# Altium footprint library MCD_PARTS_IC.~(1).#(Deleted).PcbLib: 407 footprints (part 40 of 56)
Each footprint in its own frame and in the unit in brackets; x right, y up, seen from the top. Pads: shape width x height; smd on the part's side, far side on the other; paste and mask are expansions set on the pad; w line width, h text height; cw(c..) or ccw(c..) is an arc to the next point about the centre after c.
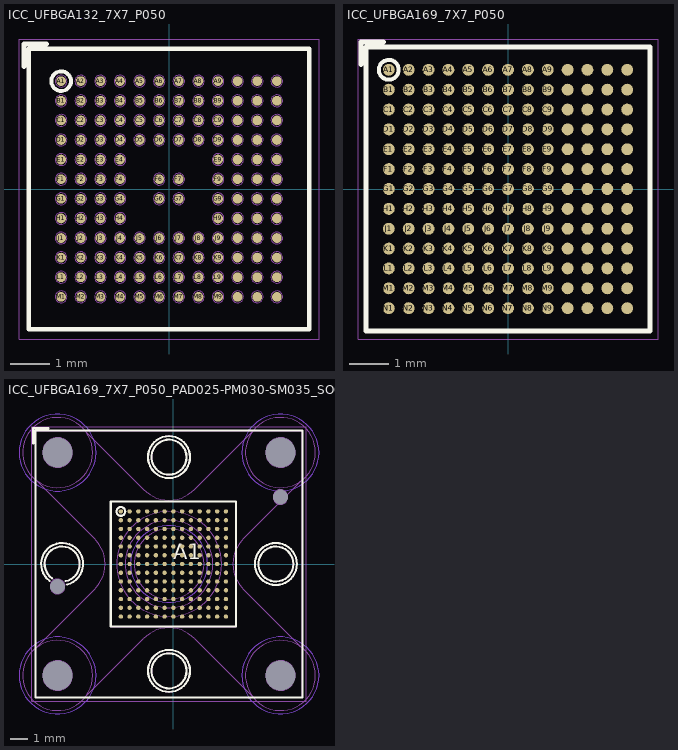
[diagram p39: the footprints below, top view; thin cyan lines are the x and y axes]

## ICC_UFBGA132_7X7_P050 [mm] "IPC"
height 0.6
pads (132):
  round 0.25 smd mask+0.05: A1(-2.75,2.75) A2(-2.25,2.75) A3(-1.75,2.75) A4(-1.25,2.75) A5(-0.75,2.75) A6(-0.25,2.75) A7(0.25,2.75) A8(0.75,2.75) A9(1.25,2.75) A10(1.75,2.75) A11(2.25,2.75) A12(2.75,2.75) B1(-2.75,2.25) B2(-2.25,2.25) B3(-1.75,2.25) B4(-1.25,2.25) B5(-0.75,2.25) B6(-0.25,2.25) B7(0.25,2.25) B8(0.75,2.25) B9(1.25,2.25) B10(1.75,2.25) B11(2.25,2.25) B12(2.75,2.25) C1(-2.75,1.75) C2(-2.25,1.75) C3(-1.75,1.75) C4(-1.25,1.75) C5(-0.75,1.75) C6(-0.25,1.75) C7(0.25,1.75) C8(0.75,1.75) C9(1.25,1.75) C10(1.75,1.75) C11(2.25,1.75) C12(2.75,1.75) D1(-2.75,1.25) D2(-2.25,1.25) D3(-1.75,1.25) D4(-1.25,1.25) D5(-0.75,1.25) D6(-0.25,1.25) D7(0.25,1.25) D8(0.75,1.25) D9(1.25,1.25) D10(1.75,1.25) D11(2.25,1.25) D12(2.75,1.25) E1(-2.75,0.75) E2(-2.25,0.75) E3(-1.75,0.75) E4(-1.25,0.75) E9(1.25,0.75) E10(1.75,0.75) E11(2.25,0.75) E12(2.75,0.75) F1(-2.75,0.25) F2(-2.25,0.25) F3(-1.75,0.25) F4(-1.25,0.25) F6(-0.25,0.25) F7(0.25,0.25) F9(1.25,0.25) F10(1.75,0.25) F11(2.25,0.25) F12(2.75,0.25) G1(-2.75,-0.25) G2(-2.25,-0.25) G3(-1.75,-0.25) G4(-1.25,-0.25) G6(-0.25,-0.25) G7(0.25,-0.25) G9(1.25,-0.25) G10(1.75,-0.25) G11(2.25,-0.25) G12(2.75,-0.25) H1(-2.75,-0.75) H2(-2.25,-0.75) H3(-1.75,-0.75) H4(-1.25,-0.75) H9(1.25,-0.75) H10(1.75,-0.75) H11(2.25,-0.75) H12(2.75,-0.75) J1(-2.75,-1.25) J2(-2.25,-1.25) J3(-1.75,-1.25) J4(-1.25,-1.25) J5(-0.75,-1.25) J6(-0.25,-1.25) J7(0.25,-1.25) J8(0.75,-1.25) J9(1.25,-1.25) J10(1.75,-1.25) J11(2.25,-1.25) J12(2.75,-1.25) K1(-2.75,-1.75) K2(-2.25,-1.75) K3(-1.75,-1.75) K4(-1.25,-1.75) K5(-0.75,-1.75) K6(-0.25,-1.75) K7(0.25,-1.75) K8(0.75,-1.75) K9(1.25,-1.75) K10(1.75,-1.75) K11(2.25,-1.75) K12(2.75,-1.75) L1(-2.75,-2.25) L2(-2.25,-2.25) L3(-1.75,-2.25) L4(-1.25,-2.25) L5(-0.75,-2.25) L6(-0.25,-2.25) L7(0.25,-2.25) L8(0.75,-2.25) L9(1.25,-2.25) L10(1.75,-2.25) L11(2.25,-2.25) L12(2.75,-2.25) M1(-2.75,-2.75) M2(-2.25,-2.75) M3(-1.75,-2.75) M4(-1.25,-2.75) M5(-0.75,-2.75) M6(-0.25,-2.75) M7(0.25,-2.75) M8(0.75,-2.75) M9(1.25,-2.75) M10(1.75,-2.75) M11(2.25,-2.75) M12(2.75,-2.75)
Top Overlay:
  circle w0.1: c-2.75,2.75 r0.25
  lines w0.12: -3.7,3.125 -3.7,3.7 -3.125,3.7 ; -3.575,-3.575 3.575,-3.575 3.575,3.575 -3.575,3.575 -3.575,-3.575
M14-Top Assembly:
  circle w0.01: c-2.75,2.75 r0.15
  circle w0.01: c-2.25,2.75 r0.15
  circle w0.01: c-1.75,2.75 r0.15
  circle w0.01: c-1.25,2.75 r0.15
  circle w0.01: c-0.75,2.75 r0.15
  circle w0.01: c-0.25,2.75 r0.15
  circle w0.01: c0.25,2.75 r0.15
  circle w0.01: c0.75,2.75 r0.15
  circle w0.01: c1.25,2.75 r0.15
  circle w0.01: c1.75,2.75 r0.15
  circle w0.01: c2.25,2.75 r0.15
  circle w0.01: c2.75,2.75 r0.15
  circle w0.01: c2.75,2.25 r0.15
  circle w0.01: c2.25,2.25 r0.15
  circle w0.01: c1.75,2.25 r0.15
  circle w0.01: c1.25,2.25 r0.15
  circle w0.01: c0.75,2.25 r0.15
  circle w0.01: c0.25,2.25 r0.15
  circle w0.01: c-0.25,2.25 r0.15
  circle w0.01: c-0.75,2.25 r0.15
  circle w0.01: c-1.25,2.25 r0.15
  circle w0.01: c-1.75,2.25 r0.15
  circle w0.01: c-2.25,2.25 r0.15
  circle w0.01: c-2.75,2.25 r0.15
  circle w0.01: c2.75,1.75 r0.15
  circle w0.01: c2.25,1.75 r0.15
  circle w0.01: c1.75,1.75 r0.15
  circle w0.01: c1.25,1.75 r0.15
  circle w0.01: c0.75,1.75 r0.15
  circle w0.01: c0.25,1.75 r0.15
  circle w0.01: c-0.25,1.75 r0.15
  circle w0.01: c-0.75,1.75 r0.15
  circle w0.01: c-1.25,1.75 r0.15
  circle w0.01: c-1.75,1.75 r0.15
  circle w0.01: c-2.25,1.75 r0.15
  circle w0.01: c-2.75,1.75 r0.15
  circle w0.01: c2.75,1.25 r0.15
  circle w0.01: c2.25,1.25 r0.15
  circle w0.01: c1.75,1.25 r0.15
  circle w0.01: c1.25,1.25 r0.15
  circle w0.01: c0.75,1.25 r0.15
  circle w0.01: c0.25,1.25 r0.15
  circle w0.01: c-0.25,1.25 r0.15
  circle w0.01: c-0.75,1.25 r0.15
  circle w0.01: c-1.25,1.25 r0.15
  circle w0.01: c-1.75,1.25 r0.15
  circle w0.01: c-2.25,1.25 r0.15
  circle w0.01: c-2.75,1.25 r0.15
  circle w0.01: c-2.75,-2.75 r0.15
  circle w0.01: c-2.25,-2.75 r0.15
  circle w0.01: c-1.75,-2.75 r0.15
  circle w0.01: c-1.25,-2.75 r0.15
  circle w0.01: c-0.75,-2.75 r0.15
  circle w0.01: c-0.25,-2.75 r0.15
  circle w0.01: c0.25,-2.75 r0.15
  circle w0.01: c0.75,-2.75 r0.15
  circle w0.01: c1.25,-2.75 r0.15
  circle w0.01: c1.75,-2.75 r0.15
  circle w0.01: c2.25,-2.75 r0.15
  circle w0.01: c2.75,-2.75 r0.15
  circle w0.01: c-2.75,-2.25 r0.15
  circle w0.01: c-2.25,-2.25 r0.15
  circle w0.01: c-1.75,-2.25 r0.15
  circle w0.01: c-1.25,-2.25 r0.15
  circle w0.01: c-0.75,-2.25 r0.15
  circle w0.01: c-0.25,-2.25 r0.15
  circle w0.01: c0.25,-2.25 r0.15
  circle w0.01: c0.75,-2.25 r0.15
  circle w0.01: c1.25,-2.25 r0.15
  circle w0.01: c1.75,-2.25 r0.15
  circle w0.01: c2.25,-2.25 r0.15
  circle w0.01: c2.75,-2.25 r0.15
  circle w0.01: c-2.75,-1.75 r0.15
  circle w0.01: c-2.25,-1.75 r0.15
  circle w0.01: c-1.75,-1.75 r0.15
  circle w0.01: c-1.25,-1.75 r0.15
  circle w0.01: c-0.75,-1.75 r0.15
  circle w0.01: c-0.25,-1.75 r0.15
  circle w0.01: c0.25,-1.75 r0.15
  circle w0.01: c0.75,-1.75 r0.15
  circle w0.01: c1.25,-1.75 r0.15
  circle w0.01: c1.75,-1.75 r0.15
  circle w0.01: c2.25,-1.75 r0.15
  circle w0.01: c2.75,-1.75 r0.15
  circle w0.01: c2.75,-1.25 r0.15
  circle w0.01: c2.25,-1.25 r0.15
  circle w0.01: c1.75,-1.25 r0.15
  circle w0.01: c1.25,-1.25 r0.15
  circle w0.01: c0.75,-1.25 r0.15
  circle w0.01: c0.25,-1.25 r0.15
  circle w0.01: c-0.25,-1.25 r0.15
  circle w0.01: c-0.75,-1.25 r0.15
  circle w0.01: c-1.25,-1.25 r0.15
  circle w0.01: c-1.75,-1.25 r0.15
  circle w0.01: c-2.25,-1.25 r0.15
  circle w0.01: c-2.75,-1.25 r0.15
  circle w0.01: c-2.75,0.75 r0.15
  circle w0.01: c-2.25,0.75 r0.15
  circle w0.01: c-1.75,0.75 r0.15
  circle w0.01: c-1.25,0.75 r0.15
  circle w0.01: c-1.25,0.25 r0.15
  circle w0.01: c-1.75,0.25 r0.15
  circle w0.01: c-2.25,0.25 r0.15
  circle w0.01: c-2.75,0.25 r0.15
  circle w0.01: c-1.25,-0.25 r0.15
  circle w0.01: c-1.75,-0.25 r0.15
  circle w0.01: c-2.25,-0.25 r0.15
  circle w0.01: c-2.75,-0.25 r0.15
  circle w0.01: c-1.25,-0.75 r0.15
  circle w0.01: c-1.75,-0.75 r0.15
  circle w0.01: c-2.25,-0.75 r0.15
  circle w0.01: c-2.75,-0.75 r0.15
  circle w0.01: c1.25,0.75 r0.15
  circle w0.01: c1.75,0.75 r0.15
  circle w0.01: c2.25,0.75 r0.15
  circle w0.01: c2.75,0.75 r0.15
  circle w0.01: c2.75,0.25 r0.15
  circle w0.01: c2.25,0.25 r0.15
  circle w0.01: c1.75,0.25 r0.15
  circle w0.01: c1.25,0.25 r0.15
  circle w0.01: c2.75,-0.25 r0.15
  circle w0.01: c2.25,-0.25 r0.15
  circle w0.01: c1.75,-0.25 r0.15
  circle w0.01: c1.25,-0.25 r0.15
  circle w0.01: c2.75,-0.75 r0.15
  circle w0.01: c2.25,-0.75 r0.15
  circle w0.01: c1.75,-0.75 r0.15
  circle w0.01: c1.25,-0.75 r0.15
  circle w0.01: c0.25,0.25 r0.15
  circle w0.01: c-0.25,0.25 r0.15
  circle w0.01: c0.25,-0.25 r0.15
  circle w0.01: c-0.25,-0.25 r0.15
  lines w0.01: -3.575,-3.575 3.575,-3.575 3.575,3.575 -3.575,3.575 -3.575,-3.575
  text "A1" at -3,2.525 h0.5
  text "'.Designator'" at -2,-0.5 h0.75
M16-Top Courtyard:
  lines w0.01: -3.825,-3.825 -3.825,3.825 3.825,3.825 3.825,-3.825 -3.825,-3.825
3D body: height 0.61, standoff 0.6, extent -3.048,2.451 -2.45,3.049
3D body: height 0.6, standoff 0.15, extent -3.575,-3.575 3.575,3.575
3D body: height 0.25, standoff -0.05, extent -2.886,2.607 -2.605,2.893
3D body: height 0.25, standoff -0.05, extent -2.386,2.607 -2.105,2.893
3D body: height 0.25, standoff -0.05, extent -1.886,2.607 -1.605,2.893
3D body: height 0.25, standoff -0.05, extent -1.386,2.607 -1.105,2.893
3D body: height 0.25, standoff -0.05, extent -0.886,2.607 -0.605,2.893
3D body: height 0.25, standoff -0.05, extent -0.386,2.607 -0.105,2.893
3D body: height 0.25, standoff -0.05, extent 0.114,2.607 0.395,2.893
3D body: height 0.25, standoff -0.05, extent 0.614,2.607 0.895,2.893
3D body: height 0.25, standoff -0.05, extent 1.114,2.607 1.395,2.893
3D body: height 0.25, standoff -0.05, extent 1.614,2.607 1.895,2.893
3D body: height 0.25, standoff -0.05, extent 2.114,2.607 2.395,2.893
3D body: height 0.25, standoff -0.05, extent 2.614,2.607 2.895,2.893
3D body: height 0.25, standoff -0.05, extent -2.886,2.107 -2.605,2.393
3D body: height 0.25, standoff -0.05, extent -2.386,2.107 -2.105,2.393
3D body: height 0.25, standoff -0.05, extent -1.886,2.107 -1.605,2.393
3D body: height 0.25, standoff -0.05, extent -1.386,2.107 -1.105,2.393
3D body: height 0.25, standoff -0.05, extent -0.886,2.107 -0.605,2.393
3D body: height 0.25, standoff -0.05, extent -0.386,2.107 -0.105,2.393
3D body: height 0.25, standoff -0.05, extent 0.114,2.107 0.395,2.393
3D body: height 0.25, standoff -0.05, extent 0.614,2.107 0.895,2.393
3D body: height 0.25, standoff -0.05, extent 1.114,2.107 1.395,2.393
3D body: height 0.25, standoff -0.05, extent 1.614,2.107 1.895,2.393
3D body: height 0.25, standoff -0.05, extent 2.114,2.107 2.395,2.393
3D body: height 0.25, standoff -0.05, extent 2.614,2.107 2.895,2.393
3D body: height 0.25, standoff -0.05, extent -0.886,1.607 -0.605,1.893
3D body: height 0.25, standoff -0.05, extent -1.386,1.607 -1.105,1.893
3D body: height 0.25, standoff -0.05, extent -1.886,1.607 -1.605,1.893
3D body: height 0.25, standoff -0.05, extent -2.386,1.607 -2.105,1.893
3D body: height 0.25, standoff -0.05, extent -2.886,1.607 -2.605,1.893
3D body: height 0.25, standoff -0.05, extent -0.386,1.607 -0.105,1.893
3D body: height 0.25, standoff -0.05, extent 0.114,1.607 0.395,1.893
3D body: height 0.25, standoff -0.05, extent 0.614,1.607 0.895,1.893
3D body: height 0.25, standoff -0.05, extent 1.114,1.607 1.395,1.893
3D body: height 0.25, standoff -0.05, extent 1.614,1.607 1.895,1.893
3D body: height 0.25, standoff -0.05, extent 2.114,1.607 2.395,1.893
3D body: height 0.25, standoff -0.05, extent 2.614,1.607 2.895,1.893
3D body: height 0.25, standoff -0.05, extent -0.886,1.107 -0.605,1.393
3D body: height 0.25, standoff -0.05, extent -1.386,1.107 -1.105,1.393
3D body: height 0.25, standoff -0.05, extent -1.886,1.107 -1.605,1.393
3D body: height 0.25, standoff -0.05, extent -2.386,1.107 -2.105,1.393
3D body: height 0.25, standoff -0.05, extent -2.886,1.107 -2.605,1.393
3D body: height 0.25, standoff -0.05, extent -0.386,1.107 -0.105,1.393
3D body: height 0.25, standoff -0.05, extent 0.114,1.107 0.395,1.393
3D body: height 0.25, standoff -0.05, extent 0.614,1.107 0.895,1.393
3D body: height 0.25, standoff -0.05, extent 1.114,1.107 1.395,1.393
3D body: height 0.25, standoff -0.05, extent 1.614,1.107 1.895,1.393
3D body: height 0.25, standoff -0.05, extent 2.114,1.107 2.395,1.393
3D body: height 0.25, standoff -0.05, extent 2.614,1.107 2.895,1.393
3D body: height 0.25, standoff -0.05, extent -0.886,-1.393 -0.605,-1.107
3D body: height 0.25, standoff -0.05, extent -1.386,-1.393 -1.105,-1.107
3D body: height 0.25, standoff -0.05, extent -1.886,-1.393 -1.605,-1.107
3D body: height 0.25, standoff -0.05, extent -2.386,-1.393 -2.105,-1.107
3D body: height 0.25, standoff -0.05, extent -2.886,-1.393 -2.605,-1.107
3D body: height 0.25, standoff -0.05, extent -0.386,-1.393 -0.105,-1.107
3D body: height 0.25, standoff -0.05, extent 0.114,-1.393 0.395,-1.107
3D body: height 0.25, standoff -0.05, extent 0.614,-1.393 0.895,-1.107
3D body: height 0.25, standoff -0.05, extent 1.114,-1.393 1.395,-1.107
3D body: height 0.25, standoff -0.05, extent 1.614,-1.393 1.895,-1.107
3D body: height 0.25, standoff -0.05, extent 2.114,-1.393 2.395,-1.107
3D body: height 0.25, standoff -0.05, extent 2.614,-1.393 2.895,-1.107
3D body: height 0.25, standoff -0.05, extent -0.886,-1.893 -0.605,-1.607
3D body: height 0.25, standoff -0.05, extent -1.386,-1.893 -1.105,-1.607
3D body: height 0.25, standoff -0.05, extent -1.886,-1.893 -1.605,-1.607
3D body: height 0.25, standoff -0.05, extent -2.386,-1.893 -2.105,-1.607
3D body: height 0.25, standoff -0.05, extent -2.886,-1.893 -2.605,-1.607
3D body: height 0.25, standoff -0.05, extent -0.386,-1.893 -0.105,-1.607
3D body: height 0.25, standoff -0.05, extent 0.114,-1.893 0.395,-1.607
3D body: height 0.25, standoff -0.05, extent 0.614,-1.893 0.895,-1.607
3D body: height 0.25, standoff -0.05, extent 1.114,-1.893 1.395,-1.607
3D body: height 0.25, standoff -0.05, extent 1.614,-1.893 1.895,-1.607
3D body: height 0.25, standoff -0.05, extent 2.114,-1.893 2.395,-1.607
3D body: height 0.25, standoff -0.05, extent 2.614,-1.893 2.895,-1.607
3D body: height 0.25, standoff -0.05, extent -0.886,-2.393 -0.605,-2.107
3D body: height 0.25, standoff -0.05, extent -1.386,-2.393 -1.105,-2.107
3D body: height 0.25, standoff -0.05, extent -1.886,-2.393 -1.605,-2.107
3D body: height 0.25, standoff -0.05, extent -2.386,-2.393 -2.105,-2.107
3D body: height 0.25, standoff -0.05, extent -2.886,-2.393 -2.605,-2.107
3D body: height 0.25, standoff -0.05, extent -0.386,-2.393 -0.105,-2.107
3D body: height 0.25, standoff -0.05, extent 0.114,-2.393 0.395,-2.107
3D body: height 0.25, standoff -0.05, extent 0.614,-2.393 0.895,-2.107
3D body: height 0.25, standoff -0.05, extent 1.114,-2.393 1.395,-2.107
3D body: height 0.25, standoff -0.05, extent 1.614,-2.393 1.895,-2.107
3D body: height 0.25, standoff -0.05, extent 2.114,-2.393 2.395,-2.107
3D body: height 0.25, standoff -0.05, extent 2.614,-2.393 2.895,-2.107
3D body: height 0.25, standoff -0.05, extent -0.886,-2.893 -0.605,-2.607
3D body: height 0.25, standoff -0.05, extent -1.386,-2.893 -1.105,-2.607
3D body: height 0.25, standoff -0.05, extent -1.886,-2.893 -1.605,-2.607
3D body: height 0.25, standoff -0.05, extent -2.386,-2.893 -2.105,-2.607
3D body: height 0.25, standoff -0.05, extent -2.886,-2.893 -2.605,-2.607
3D body: height 0.25, standoff -0.05, extent -0.386,-2.893 -0.105,-2.607
3D body: height 0.25, standoff -0.05, extent 0.114,-2.893 0.395,-2.607
3D body: height 0.25, standoff -0.05, extent 0.614,-2.893 0.895,-2.607
3D body: height 0.25, standoff -0.05, extent 1.114,-2.893 1.395,-2.607
3D body: height 0.25, standoff -0.05, extent 1.614,-2.893 1.895,-2.607
3D body: height 0.25, standoff -0.05, extent 2.114,-2.893 2.395,-2.607
3D body: height 0.25, standoff -0.05, extent 2.614,-2.893 2.895,-2.607
3D body: height 0.25, standoff -0.05, extent -1.386,0.607 -1.105,0.893
3D body: height 0.25, standoff -0.05, extent -1.886,0.607 -1.605,0.893
3D body: height 0.25, standoff -0.05, extent -2.386,0.607 -2.105,0.893
3D body: height 0.25, standoff -0.05, extent -2.886,0.607 -2.605,0.893
3D body: height 0.25, standoff -0.05, extent 1.114,0.607 1.395,0.893
3D body: height 0.25, standoff -0.05, extent 1.614,0.607 1.895,0.893
3D body: height 0.25, standoff -0.05, extent 2.114,0.607 2.395,0.893
3D body: height 0.25, standoff -0.05, extent 2.614,0.607 2.895,0.893
3D body: height 0.25, standoff -0.05, extent -1.386,0.107 -1.105,0.393
3D body: height 0.25, standoff -0.05, extent -1.886,0.107 -1.605,0.393
3D body: height 0.25, standoff -0.05, extent -2.386,0.107 -2.105,0.393
3D body: height 0.25, standoff -0.05, extent -2.886,0.107 -2.605,0.393
3D body: height 0.25, standoff -0.05, extent 1.114,0.107 1.395,0.393
3D body: height 0.25, standoff -0.05, extent 1.614,0.107 1.895,0.393
3D body: height 0.25, standoff -0.05, extent 2.114,0.107 2.395,0.393
3D body: height 0.25, standoff -0.05, extent 2.614,0.107 2.895,0.393
3D body: height 0.25, standoff -0.05, extent -1.386,-0.393 -1.105,-0.107
3D body: height 0.25, standoff -0.05, extent -1.886,-0.393 -1.605,-0.107
3D body: height 0.25, standoff -0.05, extent -2.386,-0.393 -2.105,-0.107
3D body: height 0.25, standoff -0.05, extent -2.886,-0.393 -2.605,-0.107
3D body: height 0.25, standoff -0.05, extent 1.114,-0.393 1.395,-0.107
3D body: height 0.25, standoff -0.05, extent 1.614,-0.393 1.895,-0.107
3D body: height 0.25, standoff -0.05, extent 2.114,-0.393 2.395,-0.107
3D body: height 0.25, standoff -0.05, extent 2.614,-0.393 2.895,-0.107
3D body: height 0.25, standoff -0.05, extent -1.386,-0.893 -1.105,-0.607
3D body: height 0.25, standoff -0.05, extent -1.886,-0.893 -1.605,-0.607
3D body: height 0.25, standoff -0.05, extent -2.386,-0.893 -2.105,-0.607
3D body: height 0.25, standoff -0.05, extent -2.886,-0.893 -2.605,-0.607
3D body: height 0.25, standoff -0.05, extent 1.114,-0.893 1.395,-0.607
3D body: height 0.25, standoff -0.05, extent 1.614,-0.893 1.895,-0.607
3D body: height 0.25, standoff -0.05, extent 2.114,-0.893 2.395,-0.607
3D body: height 0.25, standoff -0.05, extent 2.614,-0.893 2.895,-0.607
3D body: height 0.25, standoff -0.05, extent -0.386,0.107 -0.105,0.393
3D body: height 0.25, standoff -0.05, extent 0.114,0.107 0.395,0.393
3D body: height 0.25, standoff -0.05, extent -0.386,-0.393 -0.105,-0.107
3D body: height 0.25, standoff -0.05, extent 0.114,-0.393 0.395,-0.107

## ICC_UFBGA169_7X7_P050 [mm]
height 0.6
pads (169):
  round 0.3 smd mask+0.05: A1(-3,3) A2(-2.5,3) A3(-2,3) A4(-1.5,3) A5(-1,3) A6(-0.5,3) A7(0,3) A8(0.5,3) A9(1,3) A10(1.5,3) A11(2,3) A12(2.5,3) A13(3,3) B1(-3,2.5) B2(-2.5,2.5) B3(-2,2.5) B4(-1.5,2.5) B5(-1,2.5) B6(-0.5,2.5) B7(0,2.5) B8(0.5,2.5) B9(1,2.5) B10(1.5,2.5) B11(2,2.5) B12(2.5,2.5) B13(3,2.5) C1(-3,2) C2(-2.5,2) C3(-2,2) C4(-1.5,2) C5(-1,2) C6(-0.5,2) C7(0,2) C8(0.5,2) C9(1,2) C10(1.5,2) C11(2,2) C12(2.5,2) C13(3,2) D1(-3,1.5) D2(-2.5,1.5) D3(-2,1.5) D4(-1.5,1.5) D5(-1,1.5) D6(-0.5,1.5) D7(0,1.5) D8(0.5,1.5) D9(1,1.5) D10(1.5,1.5) D11(2,1.5) D12(2.5,1.5) D13(3,1.5) E1(-3,1) E2(-2.5,1) E3(-2,1) E4(-1.5,1) E5(-1,1) E6(-0.5,1) E7(0,1) E8(0.5,1) E9(1,1) E10(1.5,1) E11(2,1) E12(2.5,1) E13(3,1) F1(-3,0.5) F2(-2.5,0.5) F3(-2,0.5) F4(-1.5,0.5) F5(-1,0.5) F6(-0.5,0.5) F7(0,0.5) F8(0.5,0.5) F9(1,0.5) F10(1.5,0.5) F11(2,0.5) F12(2.5,0.5) F13(3,0.5) G1(-3,0) G2(-2.5,0) G3(-2,0) G4(-1.5,0) G5(-1,0) G6(-0.5,0) G7(0,0) G8(0.5,0) G9(1,0) G10(1.5,0) G11(2,0) G12(2.5,0) G13(3,0) H1(-3,-0.5) H2(-2.5,-0.5) H3(-2,-0.5) H4(-1.5,-0.5) H5(-1,-0.5) H6(-0.5,-0.5) H7(0,-0.5) H8(0.5,-0.5) H9(1,-0.5) H10(1.5,-0.5) H11(2,-0.5) H12(2.5,-0.5) H13(3,-0.5) J1(-3,-1) J2(-2.5,-1) J3(-2,-1) J4(-1.5,-1) J5(-1,-1) J6(-0.5,-1) J7(0,-1) J8(0.5,-1) J9(1,-1) J10(1.5,-1) J11(2,-1) J12(2.5,-1) J13(3,-1) K1(-3,-1.5) K2(-2.5,-1.5) K3(-2,-1.5) K4(-1.5,-1.5) K5(-1,-1.5) K6(-0.5,-1.5) K7(0,-1.5) K8(0.5,-1.5) K9(1,-1.5) K10(1.5,-1.5) K11(2,-1.5) K12(2.5,-1.5) K13(3,-1.5) L1(-3,-2) L2(-2.5,-2) L3(-2,-2) L4(-1.5,-2) L5(-1,-2) L6(-0.5,-2) L7(0,-2) L8(0.5,-2) L9(1,-2) L10(1.5,-2) L11(2,-2) L12(2.5,-2) L13(3,-2) M1(-3,-2.5) M2(-2.5,-2.5) M3(-2,-2.5) M4(-1.5,-2.5) M5(-1,-2.5) M6(-0.5,-2.5) M7(0,-2.5) M8(0.5,-2.5) M9(1,-2.5) M10(1.5,-2.5) M11(2,-2.5) M12(2.5,-2.5) M13(3,-2.5) N1(-3,-3) N2(-2.5,-3) N3(-2,-3) N4(-1.5,-3) N5(-1,-3) N6(-0.5,-3) N7(0,-3) N8(0.5,-3) N9(1,-3) N10(1.5,-3) N11(2,-3) N12(2.5,-3) N13(3,-3)
Top Overlay:
  circle w0.1: c-3,3 r0.25
  lines w0.12: -3.7,3.125 -3.7,3.7 -3.125,3.7 ; -3.575,-3.575 -3.575,3.575 3.575,3.575 3.575,-3.575 -3.575,-3.575
M14-Top Assembly:
  circle w0.01: c-3,3 r0.25
  lines w0.01: -3.575,-3.575 -3.575,3.575 3.575,3.575 3.575,-3.575 -3.575,-3.575
  text "'.Designator'" at -2,-0.5 h0.75
  text "A1" at -3.775,2.425 h0.5
M16-Top Courtyard:
  lines w0.01: -3.775,-3.775 3.775,-3.775 3.775,3.775 -3.775,3.775 -3.775,-3.775
3D body: height 0.6, standoff 0, extent -3.575,-3.575 3.575,3.575
3D body: height 0.61, standoff 0.6, extent -3.298,2.701 -2.7,3.299

## ICC_UFBGA169_7X7_P050_PAD025-PM030-SM035_SOCKET_IRONWOOD_CS1627113MF_NM [mm] "MCD-01902"
height 8.5
pads (175):
  round 0 hole 1.7 unplated mask+0.05: 0(-6.612,-6.362) 0(-6.612,6.363) 0(6.113,-6.362) 0(6.113,6.363)
  round 0 hole 0.85 unplated mask+0.05: 0(-6.612,-1.282) 0(6.113,3.823)
  round 0.25 smd paste+0.025 mask+0.05: A1(-3,3) A2(-2.5,3) A3(-2,3) A4(-1.5,3) A5(-1,3) A6(-0.5,3) A7(0,3) A8(0.5,3) A9(1,3) A10(1.5,3) A11(2,3) A12(2.5,3) A13(3,3) B1(-3,2.5) B2(-2.5,2.5) B3(-2,2.5) B4(-1.5,2.5) B5(-1,2.5) B6(-0.5,2.5) B7(0,2.5) B8(0.5,2.5) B9(1,2.5) B10(1.5,2.5) B11(2,2.5) B12(2.5,2.5) B13(3,2.5) C1(-3,2) C2(-2.5,2) C3(-2,2) C4(-1.5,2) C5(-1,2) C6(-0.5,2) C7(0,2) C8(0.5,2) C9(1,2) C10(1.5,2) C11(2,2) C12(2.5,2) C13(3,2) D1(-3,1.5) D2(-2.5,1.5) D3(-2,1.5) D4(-1.5,1.5) D5(-1,1.5) D6(-0.5,1.5) D7(0,1.5) D8(0.5,1.5) D9(1,1.5) D10(1.5,1.5) D11(2,1.5) D12(2.5,1.5) D13(3,1.5) E1(-3,1) E2(-2.5,1) E3(-2,1) E4(-1.5,1) E5(-1,1) E6(-0.5,1) E7(0,1) E8(0.5,1) E9(1,1) E10(1.5,1) E11(2,1) E12(2.5,1) E13(3,1) F1(-3,0.5) F2(-2.5,0.5) F3(-2,0.5) F4(-1.5,0.5) F5(-1,0.5) F6(-0.5,0.5) F7(0,0.5) F8(0.5,0.5) F9(1,0.5) F10(1.5,0.5) F11(2,0.5) F12(2.5,0.5) F13(3,0.5) G1(-3,0) G2(-2.5,0) G3(-2,0) G4(-1.5,0) G5(-1,0) G6(-0.5,0) G7(0,0) G8(0.5,0) G9(1,0) G10(1.5,0) G11(2,0) G12(2.5,0) G13(3,0) H1(-3,-0.5) H2(-2.5,-0.5) H3(-2,-0.5) H4(-1.5,-0.5) H5(-1,-0.5) H6(-0.5,-0.5) H7(0,-0.5) H8(0.5,-0.5) H9(1,-0.5) H10(1.5,-0.5) H11(2,-0.5) H12(2.5,-0.5) H13(3,-0.5) J1(-3,-1) J2(-2.5,-1) J3(-2,-1) J4(-1.5,-1) J5(-1,-1) J6(-0.5,-1) J7(0,-1) J8(0.5,-1) J9(1,-1) J10(1.5,-1) J11(2,-1) J12(2.5,-1) J13(3,-1) K1(-3,-1.5) K2(-2.5,-1.5) K3(-2,-1.5) K4(-1.5,-1.5) K5(-1,-1.5) K6(-0.5,-1.5) K7(0,-1.5) K8(0.5,-1.5) K9(1,-1.5) K10(1.5,-1.5) K11(2,-1.5) K12(2.5,-1.5) K13(3,-1.5) L1(-3,-2) L2(-2.5,-2) L3(-2,-2) L4(-1.5,-2) L5(-1,-2) L6(-0.5,-2) L7(0,-2) L8(0.5,-2) L9(1,-2) L10(1.5,-2) L11(2,-2) L12(2.5,-2) L13(3,-2) M1(-3,-2.5) M2(-2.5,-2.5) M3(-2,-2.5) M4(-1.5,-2.5) M5(-1,-2.5) M6(-0.5,-2.5) M7(0,-2.5) M8(0.5,-2.5) M9(1,-2.5) M10(1.5,-2.5) M11(2,-2.5) M12(2.5,-2.5) M13(3,-2.5) N1(-3,-3) N2(-2.5,-3) N3(-2,-3) N4(-1.5,-3) N5(-1,-3) N6(-0.5,-3) N7(0,-3) N8(0.5,-3) N9(1,-3) N10(1.5,-3) N11(2,-3) N12(2.5,-3) N13(3,-3)
Bottom Layer keep-out:
  circle w0.01: c-6.612,-6.362 r2.2
  circle w0.01: c6.113,-6.362 r2.2
  circle w0.01: c6.113,6.363 r2.2
  circle w0.01: c-0.25,0 r2.2
  circle w0.01: c-6.612,6.363 r2.2
Top Overlay:
  circle w0.12: c-0.25,-6.1 r1.2
  circle w0.12: c-0.25,-6.1 r1
  circle w0.12: c-0.25,6.1 r1.2
  circle w0.12: c-0.25,6.1 r1
  circle w0.12: c5.85,0 r1
  circle w0.12: c5.85,0 r1.2
  circle w0.12: c-3,3 r0.25
  circle w0.1: c-3,3 r0.25
  lines w0.12: -8,6.875 -8,7.75 -7.125,7.75 ; -7.066,-0.963 cw(c-6.35,0) -6.059,-1.164 ; -6.918,-0.823 cw(c-6.35,0) -6.154,-0.981 ; -7.862,-7.612 -7.862,7.613 7.363,7.613 7.363,-7.612 -7.862,-7.612 ; -3.575,-3.575 3.575,-3.575 3.575,3.575 -3.575,3.575 -3.575,-3.575
  text "A1" at 0,0 h1.5
Bottom Overlay:
  circle w0.12: c-6.612,6.363 r2
  circle w0.12: c6.113,6.363 r2
  circle w0.12: c-0.25,0 r2
  circle w0.12: c6.113,-6.362 r2
  circle w0.12: c-6.612,-6.362 r2
M6-Bottom Constraints:
  text "MAX / HEIGHT  / AUTHORIZED / 1.5mm" at 0,0 h0.8
  text "MAX / HEIGHT  / AUTHORIZED / 1.5mm" at 0,0 h0.8
  text "MAX / HEIGHT  / AUTHORIZED / 1.5mm" at 0,0 h0.8
  text "MAX / HEIGHT  / AUTHORIZED / 1.5mm" at 0,0 h0.8
M14-Top Assembly:
  circle w0.01: c-3,3 r0.25
  circle w0.01: c-0.25,0 r3
  circle w0.01: c-0.25,0 r2.5
  circle w0.01: c5.85,0 r1.2
  circle w0.01: c5.85,0 r1
  circle w0.01: c-0.25,6.1 r1
  circle w0.01: c-0.25,6.1 r1.2
  circle w0.01: c-6.35,0 r1
  circle w0.01: c-6.35,0 r1.2
  circle w0.01: c-0.25,-6.1 r1
  circle w0.01: c-0.25,-6.1 r1.2
  lines w0.01: -7.862,-7.612 7.363,-7.612 7.363,7.613 -7.862,7.613 -7.862,-7.612 ; -3.575,-3.575 -3.575,3.575 3.575,3.575 3.575,-3.575 -3.575,-3.575
  text "'.Designator'" at 0,0 h0.75
  text "A1" at 0,0 h0.5
M15-Bottom Assembly:
  circle w0.01: c6.113,3.823 r0.425
  circle w0.01: c-6.612,-1.282 r0.425
  circle w0.01: c6.113,-6.362 r0.85
  circle w0.01: c-6.612,-6.362 r0.85
  circle w0.01: c6.113,6.363 r0.85
  circle w0.01: c-6.612,6.363 r0.85
  circle w0.01: c-0.25,0 r2
  circle w0.01: c-6.612,6.363 r2
  circle w0.01: c6.113,6.363 r2
  circle w0.01: c6.113,-6.362 r2
  circle w0.01: c-6.612,-6.362 r2
  lines w0.01: -7.862,4.8 -4.522,1.46 ; -5.05,-7.612 -1.71,-4.272 cw(c-0.25,-5.64) 1.21,-4.273 4.555,-7.617 ; -4.522,-1.46 -7.867,-4.805 ; -4.523,-1.46 ccw(c-5.89,0) -4.523,1.46 ; 4.022,-1.46 7.363,-4.8 ; 4.022,1.46 7.368,4.805 ; 4.023,-1.46 cw(c5.39,0) 4.023,1.46 ; 4.55,7.613 1.21,4.272 cw(c-0.25,5.64) -1.71,4.273 -5.055,7.618 ; -7.867,-4.805 -7.867,-4.805 ; -5.055,7.618 -5.055,7.618 ; 4.555,-7.617 4.555,-7.617 ; 7.368,4.805 7.368,4.805
M16-Top Courtyard:
  lines w0.01: -8.075,-7.825 -8.075,7.825 7.575,7.825 7.575,-7.825 -8.075,-7.825
M17-Bottom Courtyard:
  circle w0.01: c-6.612,-6.362 r2
  circle w0.01: c6.113,-6.362 r2
  circle w0.01: c6.113,6.363 r2
  circle w0.01: c-6.612,6.363 r2
  circle w0.01: c-0.25,0 r2
  lines w0.01: -7.862,4.8 -4.522,1.46 ; -5.05,-7.612 -1.71,-4.272 cw(c-0.25,-5.64) 1.21,-4.273 4.555,-7.617 ; -4.522,-1.46 -7.867,-4.805 ; -4.523,-1.46 ccw(c-5.89,0) -4.523,1.46 ; 4.022,-1.46 7.363,-4.8 ; 4.022,1.46 7.368,4.805 ; 4.023,-1.46 cw(c5.39,0) 4.023,1.46 ; 4.55,7.613 1.21,4.272 cw(c-0.25,5.64) -1.71,4.273 -5.055,7.618 ; -7.867,-4.805 -7.867,-4.805 ; -5.055,7.618 -5.055,7.618 ; 4.555,-7.617 4.555,-7.617 ; 7.368,4.805 7.368,4.805
  text "MAX / HEIGHT  / AUTHORIZED / 1.5mm" at 0,0 h0.8
  text "MAX / HEIGHT  / AUTHORIZED / 1.5mm" at 0,0 h0.8
  text "MAX / HEIGHT  / AUTHORIZED / 1.5mm" at 0,0 h0.8
  text "MAX / HEIGHT  / AUTHORIZED / 1.5mm" at 0,0 h0.8
3D body: height 0.61, standoff 0.6, extent -3.298,2.701 -2.7,3.299
3D body: height 0.25, standoff -0.05, extent -2.136,1.857 -1.855,2.143
3D body: height 0.25, standoff -0.05, extent -1.636,1.857 -1.355,2.143
3D body: height 0.25, standoff -0.05, extent -0.636,1.857 -0.355,2.143
3D body: height 0.25, standoff -0.05, extent -0.136,1.857 0.145,2.143
3D body: height 0.25, standoff -0.05, extent 0.864,1.857 1.145,2.143
3D body: height 0.25, standoff -0.05, extent 1.364,1.857 1.645,2.143
3D body: height 0.25, standoff -0.05, extent 1.864,1.857 2.145,2.143
3D body: height 0.25, standoff -0.05, extent -2.136,1.357 -1.855,1.643
3D body: height 0.25, standoff -0.05, extent -1.636,1.357 -1.355,1.643
3D body: height 0.25, standoff -0.05, extent -1.136,1.357 -0.855,1.643
3D body: height 0.25, standoff -0.05, extent -0.636,1.357 -0.355,1.643
3D body: height 0.25, standoff -0.05, extent -0.136,1.357 0.145,1.643
3D body: height 0.25, standoff -0.05, extent 0.364,1.357 0.645,1.643
3D body: height 0.25, standoff -0.05, extent 0.864,1.357 1.145,1.643
3D body: height 0.25, standoff -0.05, extent 1.364,1.357 1.645,1.643
3D body: height 0.25, standoff -0.05, extent 1.864,1.357 2.145,1.643
3D body: height 0.25, standoff -0.05, extent -1.136,0.857 -0.855,1.143
3D body: height 0.25, standoff -0.05, extent 0.364,0.857 0.645,1.143
3D body: height 0.25, standoff -0.05, extent 1.864,0.357 2.145,0.643
3D body: height 0.25, standoff -0.05, extent 1.364,0.357 1.645,0.643
3D body: height 0.25, standoff -0.05, extent 0.864,0.357 1.145,0.643
3D body: height 0.25, standoff -0.05, extent 0.364,0.357 0.645,0.643
3D body: height 0.25, standoff -0.05, extent -0.136,0.357 0.145,0.643
3D body: height 0.25, standoff -0.05, extent -0.636,0.357 -0.355,0.643
3D body: height 0.25, standoff -0.05, extent -1.136,0.357 -0.855,0.643
3D body: height 0.25, standoff -0.05, extent -1.636,0.357 -1.355,0.643
3D body: height 0.25, standoff -0.05, extent 1.364,0.857 1.645,1.143
3D body: height 0.25, standoff -0.05, extent 0.864,0.857 1.145,1.143
3D body: height 0.25, standoff -0.05, extent -0.136,0.857 0.145,1.143
3D body: height 0.25, standoff -0.05, extent -0.636,0.857 -0.355,1.143
3D body: height 0.25, standoff -0.05, extent -1.636,0.857 -1.355,1.143
3D body: height 0.25, standoff -0.05, extent -2.136,0.857 -1.855,1.143
3D body: height 0.25, standoff -0.05, extent -1.636,-1.143 -1.355,-0.857
3D body: height 0.25, standoff -0.05, extent -0.636,-1.143 -0.355,-0.857
3D body: height 0.25, standoff -0.05, extent -0.136,-1.143 0.145,-0.857
3D body: height 0.25, standoff -0.05, extent 0.864,-1.143 1.145,-0.857
3D body: height 0.25, standoff -0.05, extent 1.364,-1.143 1.645,-0.857
3D body: height 0.25, standoff -0.05, extent 1.864,-1.143 2.145,-0.857
3D body: height 0.25, standoff -0.05, extent -2.136,-1.643 -1.855,-1.357
3D body: height 0.25, standoff -0.05, extent -1.636,-1.643 -1.355,-1.357
3D body: height 0.25, standoff -0.05, extent -1.136,-1.643 -0.855,-1.357
3D body: height 0.25, standoff -0.05, extent -0.636,-1.643 -0.355,-1.357
3D body: height 0.25, standoff -0.05, extent -0.136,-1.643 0.145,-1.357
3D body: height 0.25, standoff -0.05, extent 0.364,-1.643 0.645,-1.357
3D body: height 0.25, standoff -0.05, extent 0.864,-1.643 1.145,-1.357
3D body: height 0.25, standoff -0.05, extent 1.364,-1.643 1.645,-1.357
3D body: height 0.25, standoff -0.05, extent 1.864,-1.643 2.145,-1.357
3D body: height 0.25, standoff -0.05, extent 0.364,-1.143 0.645,-0.857
3D body: height 0.25, standoff -0.05, extent -1.136,-1.143 -0.855,-0.857
3D body: height 0.25, standoff -0.05, extent -1.136,-0.143 -0.855,0.143
3D body: height 0.25, standoff -0.05, extent 0.364,-0.143 0.645,0.143
3D body: height 0.25, standoff -0.05, extent 1.364,-0.643 1.645,-0.357
3D body: height 0.25, standoff -0.05, extent 0.864,-0.643 1.145,-0.357
3D body: height 0.25, standoff -0.05, extent 0.364,-0.643 0.645,-0.357
3D body: height 0.25, standoff -0.05, extent -0.136,-0.643 0.145,-0.357
3D body: height 0.25, standoff -0.05, extent -0.636,-0.643 -0.355,-0.357
3D body: height 0.25, standoff -0.05, extent -1.136,-0.643 -0.855,-0.357
3D body: height 0.25, standoff -0.05, extent -1.636,-0.643 -1.355,-0.357
3D body: height 0.25, standoff -0.05, extent -2.136,-0.643 -1.855,-0.357
3D body: height 0.25, standoff -0.05, extent 1.864,-0.143 2.145,0.143
3D body: height 0.25, standoff -0.05, extent 1.364,-0.143 1.645,0.143
3D body: height 0.25, standoff -0.05, extent 0.864,-0.143 1.145,0.143
3D body: height 0.25, standoff -0.05, extent -0.136,-0.143 0.145,0.143
3D body: height 0.25, standoff -0.05, extent -0.636,-0.143 -0.355,0.143
3D body: height 0.25, standoff -0.05, extent -1.636,-0.143 -1.355,0.143
3D body: height 0.25, standoff -0.05, extent -2.136,-0.143 -1.855,0.143
3D body: height 0.25, standoff -0.05, extent 1.864,-2.143 2.145,-1.857
3D body: height 0.25, standoff -0.05, extent 1.364,-2.143 1.645,-1.857
3D body: height 0.25, standoff -0.05, extent 0.364,-2.143 0.645,-1.857
3D body: height 0.25, standoff -0.05, extent -0.136,-2.143 0.145,-1.857
3D body: height 0.25, standoff -0.05, extent -1.136,-2.143 -0.855,-1.857
3D body: height 0.25, standoff -0.05, extent -1.636,-2.143 -1.355,-1.857
3D body: height 0.25, standoff -0.05, extent -2.136,-2.143 -1.855,-1.857
3D body: height 0.25, standoff -0.05, extent -1.136,1.857 -0.855,2.143
3D body: height 0.25, standoff -0.05, extent 0.364,1.857 0.645,2.143
3D body: height 0.25, standoff -0.05, extent -2.136,0.357 -1.855,0.643
3D body: height 0.25, standoff -0.05, extent 1.864,0.857 2.145,1.143
3D body: height 0.25, standoff -0.05, extent 1.864,-0.643 2.145,-0.357
3D body: height 0.25, standoff -0.05, extent -2.136,-1.143 -1.855,-0.857
3D body: height 0.25, standoff -0.05, extent -2.636,1.857 -2.355,2.143
3D body: height 0.25, standoff -0.05, extent -3.136,1.857 -2.855,2.143
3D body: height 0.25, standoff -0.05, extent 2.364,1.857 2.645,2.143
3D body: height 0.25, standoff -0.05, extent 2.864,1.857 3.145,2.143
3D body: height 0.25, standoff -0.05, extent -0.136,2.357 0.145,2.643
3D body: height 0.25, standoff -0.05, extent -0.136,2.857 0.145,3.143
3D body: height 0.25, standoff -0.05, extent -0.136,-2.643 0.145,-2.357
3D body: height 0.25, standoff -0.05, extent -0.136,-3.143 0.145,-2.857
3D body: height 0.25, standoff -0.05, extent -0.636,-2.143 -0.355,-1.857
3D body: height 0.25, standoff -0.05, extent 0.864,-2.143 1.145,-1.857
3D body: height 0.25, standoff -0.05, extent 2.864,1.357 3.145,1.643
3D body: height 0.25, standoff -0.05, extent 2.364,1.357 2.645,1.643
3D body: height 0.25, standoff -0.05, extent 2.864,0.857 3.145,1.143
3D body: height 0.25, standoff -0.05, extent 2.364,0.857 2.645,1.143
3D body: height 0.25, standoff -0.05, extent 2.864,0.357 3.145,0.643
3D body: height 0.25, standoff -0.05, extent 2.364,0.357 2.645,0.643
3D body: height 0.25, standoff -0.05, extent 2.864,-0.143 3.145,0.143
3D body: height 0.25, standoff -0.05, extent 2.364,-0.143 2.645,0.143
3D body: height 0.25, standoff -0.05, extent 2.864,-0.643 3.145,-0.357
3D body: height 0.25, standoff -0.05, extent 2.364,-0.643 2.645,-0.357
3D body: height 0.25, standoff -0.05, extent 2.864,-1.143 3.145,-0.857
3D body: height 0.25, standoff -0.05, extent 2.364,-1.143 2.645,-0.857
3D body: height 0.25, standoff -0.05, extent 2.864,-1.643 3.145,-1.357
3D body: height 0.25, standoff -0.05, extent 2.364,-1.643 2.645,-1.357
3D body: height 0.25, standoff -0.05, extent 2.864,-2.143 3.145,-1.857
3D body: height 0.25, standoff -0.05, extent 2.364,-2.143 2.645,-1.857
3D body: height 0.25, standoff -0.05, extent -2.636,1.357 -2.355,1.643
3D body: height 0.25, standoff -0.05, extent -3.136,1.357 -2.855,1.643
3D body: height 0.25, standoff -0.05, extent -2.636,0.857 -2.355,1.143
3D body: height 0.25, standoff -0.05, extent -3.136,0.857 -2.855,1.143
3D body: height 0.25, standoff -0.05, extent -2.636,0.357 -2.355,0.643
3D body: height 0.25, standoff -0.05, extent -3.136,0.357 -2.855,0.643
3D body: height 0.25, standoff -0.05, extent -2.636,-0.143 -2.355,0.143
3D body: height 0.25, standoff -0.05, extent -3.136,-0.143 -2.855,0.143
3D body: height 0.25, standoff -0.05, extent -2.636,-0.643 -2.355,-0.357
3D body: height 0.25, standoff -0.05, extent -3.136,-0.643 -2.855,-0.357
3D body: height 0.25, standoff -0.05, extent -2.636,-1.143 -2.355,-0.857
3D body: height 0.25, standoff -0.05, extent -3.136,-1.143 -2.855,-0.857
3D body: height 0.25, standoff -0.05, extent -2.636,-1.643 -2.355,-1.357
3D body: height 0.25, standoff -0.05, extent -3.136,-1.643 -2.855,-1.357
3D body: height 0.25, standoff -0.05, extent -2.636,-2.143 -2.355,-1.857
3D body: height 0.25, standoff -0.05, extent -3.136,-2.143 -2.855,-1.857
3D body: height 0.25, standoff -0.05, extent -3.136,2.357 -2.855,2.643
3D body: height 0.25, standoff -0.05, extent -2.636,2.357 -2.355,2.643
3D body: height 0.25, standoff -0.05, extent -1.136,2.357 -0.855,2.643
3D body: height 0.25, standoff -0.05, extent -0.636,2.357 -0.355,2.643
3D body: height 0.25, standoff -0.05, extent -1.636,2.357 -1.355,2.643
3D body: height 0.25, standoff -0.05, extent -2.136,2.357 -1.855,2.643
3D body: height 0.25, standoff -0.05, extent -3.136,2.857 -2.855,3.143
3D body: height 0.25, standoff -0.05, extent -2.636,2.857 -2.355,3.143
3D body: height 0.25, standoff -0.05, extent -1.136,2.857 -0.855,3.143
3D body: height 0.25, standoff -0.05, extent -0.636,2.857 -0.355,3.143
3D body: height 0.25, standoff -0.05, extent -1.636,2.857 -1.355,3.143
3D body: height 0.25, standoff -0.05, extent -2.136,2.857 -1.855,3.143
3D body: height 0.25, standoff -0.05, extent 0.364,2.357 0.645,2.643
3D body: height 0.25, standoff -0.05, extent 0.864,2.357 1.145,2.643
3D body: height 0.25, standoff -0.05, extent 2.364,2.357 2.645,2.643
3D body: height 0.25, standoff -0.05, extent 2.864,2.357 3.145,2.643
3D body: height 0.25, standoff -0.05, extent 1.864,2.357 2.145,2.643
3D body: height 0.25, standoff -0.05, extent 1.364,2.357 1.645,2.643
3D body: height 0.25, standoff -0.05, extent 0.364,2.857 0.645,3.143
3D body: height 0.25, standoff -0.05, extent 0.864,2.857 1.145,3.143
3D body: height 0.25, standoff -0.05, extent 2.364,2.857 2.645,3.143
3D body: height 0.25, standoff -0.05, extent 2.864,2.857 3.145,3.143
3D body: height 0.25, standoff -0.05, extent 1.864,2.857 2.145,3.143
3D body: height 0.25, standoff -0.05, extent 1.364,2.857 1.645,3.143
3D body: height 0.25, standoff -0.05, extent -3.136,-2.643 -2.855,-2.357
3D body: height 0.25, standoff -0.05, extent -2.636,-2.643 -2.355,-2.357
3D body: height 0.25, standoff -0.05, extent -1.136,-2.643 -0.855,-2.357
3D body: height 0.25, standoff -0.05, extent -0.636,-2.643 -0.355,-2.357
3D body: height 0.25, standoff -0.05, extent -1.636,-2.643 -1.355,-2.357
3D body: height 0.25, standoff -0.05, extent -2.136,-2.643 -1.855,-2.357
3D body: height 0.25, standoff -0.05, extent -3.136,-3.143 -2.855,-2.857
3D body: height 0.25, standoff -0.05, extent -2.636,-3.143 -2.355,-2.857
3D body: height 0.25, standoff -0.05, extent -1.136,-3.143 -0.855,-2.857
3D body: height 0.25, standoff -0.05, extent -0.636,-3.143 -0.355,-2.857
3D body: height 0.25, standoff -0.05, extent -1.636,-3.143 -1.355,-2.857
3D body: height 0.25, standoff -0.05, extent -2.136,-3.143 -1.855,-2.857
3D body: height 0.25, standoff -0.05, extent 0.364,-2.643 0.645,-2.357
3D body: height 0.25, standoff -0.05, extent 0.864,-2.643 1.145,-2.357
3D body: height 0.25, standoff -0.05, extent 2.364,-2.643 2.645,-2.357
3D body: height 0.25, standoff -0.05, extent 2.864,-2.643 3.145,-2.357
3D body: height 0.25, standoff -0.05, extent 1.864,-2.643 2.145,-2.357
3D body: height 0.25, standoff -0.05, extent 1.364,-2.643 1.645,-2.357
3D body: height 0.25, standoff -0.05, extent 0.364,-3.143 0.645,-2.857
3D body: height 0.25, standoff -0.05, extent 0.864,-3.143 1.145,-2.857
3D body: height 0.25, standoff -0.05, extent 2.364,-3.143 2.645,-2.857
3D body: height 0.25, standoff -0.05, extent 2.864,-3.143 3.145,-2.857
3D body: height 0.25, standoff -0.05, extent 1.864,-3.143 2.145,-2.857
3D body: height 0.25, standoff -0.05, extent 1.364,-3.143 1.645,-2.857
3D body: height 0.6, standoff 0.15, extent -3.5,-3.5 3.5,3.5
